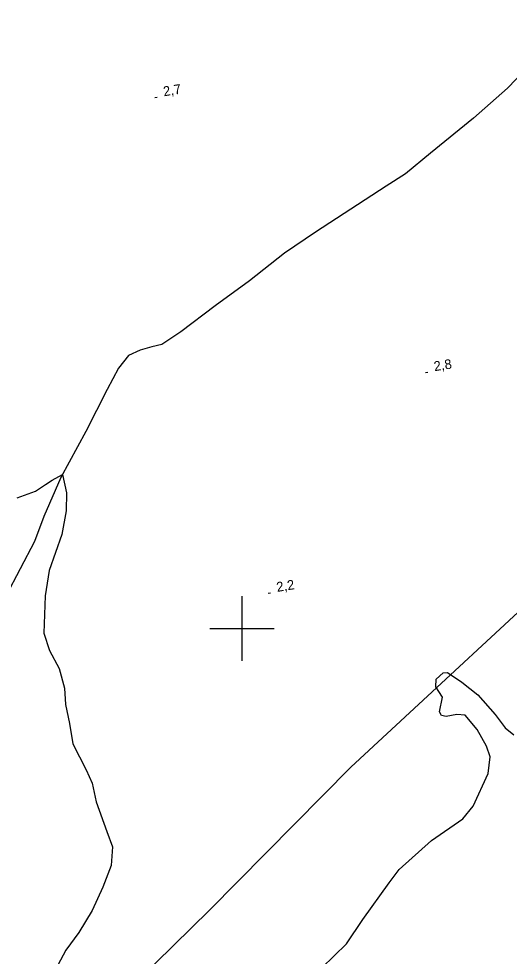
# Model space of a CAD drawing. Extents: x 643342 to 646936, y 5873857 to 5876103.
# Drawn here: x 645130.8 to 645282.9, y 5874698.4 to 5874989 of the extents above; entities that cross this region are included whole.
import ezdxf

# ---------------------------------------------------------------- set-up
doc = ezdxf.new("R2010")
doc.units = 0
for name, color, linetype in [('Niveau 2', 7, 'Continuous'), ('Niveau 3', 7, 'Continuous'), ('Niveau 4', 7, 'Continuous'), ('Niveau 61', 7, 'Continuous')]:
    doc.layers.add(name, color=color, linetype=linetype)

msp = doc.modelspace()

# ---------------------------------------------------------------- linework, layer by layer
at = {"layer": 'Niveau 2'}
for points in [[(645150.74, 5874674.21), (645189.93, 5874712.68), (645233.73, 5874757.01), (645308.06, 5874825.78), (645368.92, 5874885.42)], [(645130.35, 5874840.5), (645136, 5874842.53), (645139.11, 5874844.63), (645141.14, 5874846.01), (645144.4, 5874847.77), (645145.61, 5874842.08), (645145.52, 5874836.48), (645144.13, 5874829.14), (645140.29, 5874817.95), (645139.05, 5874810.14), (645138.6, 5874798.57), (645140.32, 5874793.22), (645143.36, 5874787.59), (645144.96, 5874781.51), (645145.3, 5874776.48), (645146.53, 5874770.56), (645147.55, 5874764.26), (645151.76, 5874756.22), (645153.52, 5874752), (645154.8, 5874746.26), (645158.08, 5874737.09), (645159.87, 5874732.34), (645159.44, 5874726.55), (645156.83, 5874719.85), (645153.62, 5874712.52), (645149.47, 5874705.78), (645145.37, 5874700.23), (645142.13, 5874694.08)], [(645224.72, 5874694.82), (645232.45, 5874702.2), (645237.47, 5874709.75), (645245.63, 5874721.17), (645248.76, 5874725.29), (645258.74, 5874734.22), (645268.5, 5874741.02), (645271.65, 5874744.89), (645276.37, 5874755.03), (645276.97, 5874760.16), (645275.86, 5874763.52), (645272.93, 5874768.67), (645269.17, 5874773.1), (645266.63, 5874773.29), (645263.32, 5874772.66), (645261.83, 5874773.04), (645261.22, 5874774.19), (645262.21, 5874778.75), (645260.12, 5874781.88), (645260.19, 5874784.31), (645262.41, 5874786.29), (645263.76, 5874786.32), (645268.19, 5874783.35), (645273.15, 5874779.46), (645278.5, 5874773.29), (645281.59, 5874769.17), (645284.32, 5874767.03)]]:
    msp.add_lwpolyline(points, dxfattribs=at)
at = {"layer": 'Niveau 3'}
for p, q in [((645172.97, 5874964.56), (645173.76, 5874964.69)), ((645256.88, 5874879.35), (645257.67, 5874879.47)), ((645208.09, 5874810.93), (645208.88, 5874811.05))]:
    msp.add_line(p, q, dxfattribs=at)
at = {"layer": 'Niveau 4'}
for points in [[(645301.14, 5874992.82), (645295.93, 5874982.89), (645290.14, 5874975.61), (645282.31, 5874967.54), (645271.78, 5874958.15), (645258.44, 5874947.3), (645250.69, 5874940.89), (645244.69, 5874937.12), (645222.84, 5874922.84), (645213.2, 5874916.35), (645202.34, 5874907.73), (645191.75, 5874899.97), (645181.06, 5874891.96), (645175.18, 5874888.07), (645172.07, 5874887.3), (645168.4, 5874886.23), (645164.79, 5874884.58), (645161.72, 5874880.73), (645158.19, 5874874.12), (645151.58, 5874861.06), (645143.89, 5874846.83)], [(645143.89, 5874846.83), (645138.57, 5874834.71), (645135.68, 5874826.91), (645126.79, 5874810.04)]]:
    msp.add_lwpolyline(points, dxfattribs=at)
at = {"layer": 'Niveau 61'}
for points in [[(645200, 5874810), (645200, 5874800), (645200, 5874790)], [(645190, 5874800), (645200, 5874800), (645210, 5874800)]]:
    msp.add_lwpolyline(points, dxfattribs=at)

# ---------------------------------------------------------------- texts
at = {"layer": 'Niveau 3'}
for s, rotation, p in [('2,7  ', 8.9405, (645175.82, 5874964.97)), ('2,8  ', 8.941, (645259.73, 5874879.75)), ('2,2  ', 8.941, (645210.94, 5874811.33))]:
    msp.add_text(s, height=3, rotation=rotation, dxfattribs=at).set_placement(p)

doc.saveas('drawing.dxf')
